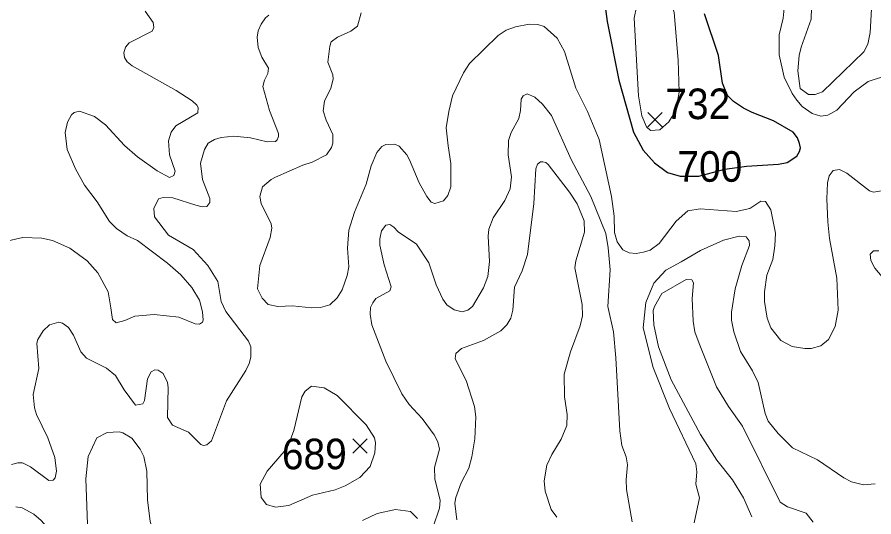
# Model space of a CAD drawing. Extents: x 294.2 to 320.3, y 7482.7 to 7510.7.
# Drawn here: x 303.455 to 305.694, y 7490.851 to 7492.157 of the extents above; entities that cross this region are included whole.
import ezdxf
from ezdxf.enums import TextEntityAlignment as Align

# ---------------------------------------------------------------- set-up
doc = ezdxf.new("R2010")
doc.units = 0
doc.header["$LTSCALE"] = 0.032
for name, color, linetype, lineweight in [('1', 7, 'Continuous', 25), ('2', 7, 'Continuous', 13), ('21', 7, 'Continuous', 25)]:
    doc.layers.add(name, color=color, linetype=linetype, lineweight=lineweight)
doc.layers.add('61', color=7, linetype='Continuous')

msp = doc.modelspace()

# ---------------------------------------------------------------- linework, layer by layer
at = {"layer": '1'}
for points in [[(304.9833, 7492.2509), (304.9973, 7492.1456), (305.0273, 7491.9923), (305.0656, 7491.857), (305.0912, 7491.8098), (305.1211, 7491.7761), (305.1544, 7491.7511), (305.1876, 7491.7413), (305.2367, 7491.7418), (305.3048, 7491.7599), (305.3607, 7491.7675), (305.4443, 7491.7728), (305.467, 7491.7773)], [(305.483, 7491.8564), (305.4317, 7491.8859), (305.3759, 7491.9078), (305.3532, 7491.9198), (305.3268, 7491.9372), (305.3117, 7491.9523), (305.2988, 7491.9848), (305.2883, 7492.0573), (305.2517, 7492.1661)], [(305.467, 7491.7773), (305.4929, 7491.7937), (305.4997, 7491.8058), (305.5019, 7491.8156), (305.4997, 7491.827), (305.4944, 7491.8421), (305.483, 7491.8564)]]:
    msp.add_lwpolyline(points, dxfattribs=at)
at = {"layer": '2'}
for points in [[(305.0675, 7492.1546), (305.079, 7491.9515), (305.0874, 7491.8992), (305.0996, 7491.8704), (305.1101, 7491.8607), (305.1346, 7491.8629), (305.1584, 7491.8838), (305.1762, 7491.9134), (305.1851, 7491.9613), (305.1825, 7492.0448), (305.1722, 7492.1699), (305.1659, 7492.1929), (305.1588, 7492.2056), (305.1429, 7492.2216), (305.1276, 7492.2222), (305.1123, 7492.219), (305.0905, 7492.2075), (305.0739, 7492.1839)], [(304.1066, 7490.8833), (304.0932, 7490.9012), (304.0907, 7490.9364), (304.1086, 7490.9708), (304.1533, 7491.0217), (304.1644, 7491.039), (304.1788, 7491.0768), (304.1992, 7491.1649), (304.2081, 7491.1796), (304.2248, 7491.1924), (304.258, 7491.1879), (304.2918, 7491.1681), (304.3678, 7491.0915), (304.3895, 7491.0577), (304.392, 7491.0449), (304.3901, 7491.0181), (304.378, 7490.9829), (304.3506, 7490.9542), (304.3129, 7490.9319), (304.2861, 7490.9217), (304.2273, 7490.9076), (304.1654, 7490.8808), (304.1303, 7490.8763)]]:
    msp.add_lwpolyline(points, close=True, dxfattribs=at)
for points in [[(305.7188, 7492.002), (305.6792, 7491.9892), (305.6422, 7491.9617), (305.5975, 7491.9139), (305.5733, 7491.9011), (305.5554, 7491.8985), (305.5324, 7491.9055), (305.5062, 7491.9234), (305.4922, 7491.94), (305.48, 7491.9579), (305.4596, 7492.0001), (305.4462, 7492.0588), (305.4468, 7492.1112), (305.457, 7492.1546), (305.4615, 7492.198)], [(303.4203, 7491.5704), (303.4701, 7491.5812), (303.5199, 7491.5793), (303.548, 7491.5735), (303.5927, 7491.5538), (303.638, 7491.5206), (303.6661, 7491.4893), (303.6935, 7491.4395), (303.6999, 7491.3973), (303.705, 7491.3667), (303.714, 7491.3584), (303.737, 7491.3641), (303.7625, 7491.3756), (303.8136, 7491.3801), (303.8775, 7491.373), (303.9209, 7491.3558), (303.9323, 7491.3546), (303.94, 7491.3603), (303.9413, 7491.3648), (303.94, 7491.3871), (303.9323, 7491.4178), (303.9119, 7491.451), (303.8832, 7491.4835), (303.8487, 7491.5142), (303.7695, 7491.5735), (303.7427, 7491.5857), (303.7153, 7491.6048), (303.6968, 7491.6233), (303.6648, 7491.6744), (303.631, 7491.7179), (303.608, 7491.7606), (303.5863, 7491.8111), (303.5812, 7491.8558), (303.5869, 7491.8826), (303.5972, 7491.9017), (303.6042, 7491.9081), (303.6182, 7491.9119), (303.6578, 7491.8973), (303.6865, 7491.8761), (303.7357, 7491.8219), (303.7695, 7491.7919), (303.8213, 7491.7555), (303.8532, 7491.7382), (303.8647, 7491.7434), (303.8679, 7491.7549), (303.8532, 7491.797), (303.8513, 7491.8341), (303.8577, 7491.857), (303.8704, 7491.873), (303.9279, 7491.9068), (303.9285, 7491.9209), (303.9247, 7491.9273), (303.9126, 7491.9387), (303.8711, 7491.9655), (303.7562, 7492.0301), (303.7427, 7492.0409), (303.7363, 7492.0518), (303.7344, 7492.0639), (303.7389, 7492.0786), (303.7484, 7492.0901), (303.8085, 7492.1207), (303.8123, 7492.1303), (303.8104, 7492.1431), (303.79, 7492.173)], [(305.5311, 7492.1827), (305.5298, 7492.152), (305.5043, 7492.0792), (305.4991, 7492.0575), (305.4953, 7492.0167), (305.5011, 7491.9707), (305.5228, 7491.9553), (305.5401, 7491.9553), (305.5598, 7491.9624), (305.6677, 7492.0665), (305.6779, 7492.0869), (305.6843, 7492.1175), (305.6881, 7492.1788)], [(303.9508, 7491.6623), (303.9585, 7491.6732), (303.9591, 7491.6834), (303.9394, 7491.7332), (303.9349, 7491.7753), (303.9451, 7491.8111), (303.9547, 7491.8277), (303.9707, 7491.8372), (303.9886, 7491.8423), (304.0218, 7491.8462), (304.0652, 7491.8417), (304.1086, 7491.8315), (304.1303, 7491.8321), (304.1347, 7491.8366), (304.1386, 7491.8455), (304.1379, 7491.8532), (304.1149, 7491.9132), (304.0977, 7491.9758), (304.1016, 7491.9924), (304.1105, 7492.0103), (304.1124, 7492.0237), (304.0945, 7492.0524), (304.085, 7492.078), (304.083, 7492.1048), (304.0856, 7492.1214), (304.0926, 7492.1392), (304.1041, 7492.1558), (304.113, 7492.1629)], [(304.3544, 7492.1686), (304.3448, 7492.1341), (304.3275, 7492.1207), (304.2925, 7492.1054)], [(304.2752, 7491.972), (304.2586, 7491.9375), (304.2548, 7491.912), (304.2625, 7491.8877), (304.2803, 7491.8507), (304.2803, 7491.8277), (304.2771, 7491.8162), (304.2637, 7491.7976), (304.2261, 7491.7785), (304.2018, 7491.7708), (304.1303, 7491.7389), (304.1188, 7491.7331), (304.0964, 7491.714), (304.0894, 7491.6885), (304.0926, 7491.67), (304.1194, 7491.617), (304.1207, 7491.6055), (304.1169, 7491.5812), (304.0894, 7491.5084), (304.0837, 7491.4471), (304.0958, 7491.4229), (304.1111, 7491.4062), (304.1367, 7491.4005), (304.175, 7491.4031), (304.2248, 7491.3973), (304.2478, 7491.398), (304.272, 7491.405), (304.2912, 7491.4235), (304.3046, 7491.4446), (304.318, 7491.4816), (304.3225, 7491.5046), (304.3186, 7491.5531), (304.3218, 7491.6004), (304.3371, 7491.6476), (304.3678, 7491.7204), (304.3805, 7491.7689), (304.3953, 7491.8034), (304.408, 7491.8194), (304.4189, 7491.8245), (304.4419, 7491.8257), (304.4534, 7491.82), (304.4738, 7491.797), (304.4808, 7491.7843), (304.5057, 7491.7242), (304.5255, 7491.6885), (304.537, 7491.6738), (304.5466, 7491.6706), (304.5696, 7491.677), (304.5804, 7491.691), (304.5887, 7491.714), (304.5887, 7491.7746), (304.5817, 7491.8213), (304.5768, 7491.868), (304.5831, 7491.9106), (304.5932, 7491.9515), (304.6213, 7492.0116), (304.6372, 7492.0358), (304.7126, 7492.1098), (304.733, 7492.1233), (304.7573, 7492.1322), (304.793, 7492.1386), (304.816, 7492.1379), (304.8326, 7492.1328), (304.8664, 7492.1028), (304.8856, 7492.0677), (304.9156, 7491.972), (304.9456, 7491.9107), (304.9763, 7491.8379), (305.0088, 7491.6885), (305.0152, 7491.6374), (305.0165, 7491.594), (305.0228, 7491.5697), (305.0382, 7491.5492), (305.0548, 7491.541), (305.0727, 7491.5397), (305.0918, 7491.5429), (305.1097, 7491.5486), (305.1327, 7491.5652), (305.1774, 7491.624), (305.208, 7491.6514), (305.24, 7491.6565), (305.3345, 7491.6495), (305.3702, 7491.6572), (305.3983, 7491.6763), (305.4104, 7491.6751), (305.4251, 7491.654), (305.4366, 7491.5927), (305.4353, 7491.5595), (305.4296, 7491.5238), (305.4143, 7491.4829), (305.4079, 7491.4395), (305.4079, 7491.4139), (305.4155, 7491.3705), (305.4245, 7491.345), (305.4506, 7491.3124)], [(304.2925, 7492.1054), (304.2758, 7492.0926), (304.2727, 7492.0818), (304.2676, 7492.0396), (304.2803, 7492.0064), (304.2809, 7491.995), (304.2752, 7491.972)], [(304.8083, 7491.9483), (304.7879, 7491.9566), (304.7777, 7491.9515), (304.772, 7491.9426), (304.7707, 7491.9132), (304.7662, 7491.8928), (304.7464, 7491.8558), (304.7394, 7491.8353), (304.7381, 7491.797), (304.747, 7491.7396), (304.7432, 7491.7089), (304.7298, 7491.6783), (304.6992, 7491.6323), (304.6883, 7491.6029), (304.6857, 7491.585), (304.6896, 7491.5186), (304.6851, 7491.4791), (304.6736, 7491.4497), (304.6449, 7491.4012), (304.6334, 7491.3916), (304.618, 7491.3871), (304.597, 7491.3922), (304.5785, 7491.405), (304.5676, 7491.4203), (304.5504, 7491.4574), (304.5312, 7491.5148), (304.4987, 7491.5639), (304.4514, 7491.596), (304.4393, 7491.6087), (304.4291, 7491.6151), (304.4189, 7491.6138), (304.4074, 7491.5984), (304.4029, 7491.5774), (304.4035, 7491.5614), (304.4144, 7491.5097), (304.4323, 7491.4522), (304.4291, 7491.442), (304.3927, 7491.4216), (304.3844, 7491.4101), (304.3787, 7491.3979), (304.3774, 7491.3807), (304.3818, 7491.3526), (304.4188, 7491.2581), (304.4604, 7491.1726), (304.4801, 7491.1445), (304.5133, 7491.1081), (304.5453, 7491.0653), (304.5549, 7491.0475), (304.5593, 7491.0283), (304.5459, 7490.9798), (304.5472, 7490.9504), (304.5606, 7490.8942), (304.5593, 7490.8738), (304.5421, 7490.8253)], [(304.9999, 7491.5544), (304.9935, 7491.5914), (304.9546, 7491.6885), (304.9028, 7491.7855), (304.8517, 7491.9005), (304.8281, 7491.9298), (304.8083, 7491.9483)], [(304.8658, 7490.8502), (304.8511, 7490.87), (304.8351, 7490.9185), (304.8326, 7490.9453), (304.8396, 7490.9862), (304.8524, 7491.0143), (304.8773, 7491.0538), (304.8913, 7491.0896), (304.8926, 7491.119), (304.8856, 7491.1649), (304.8849, 7491.2237), (304.9015, 7491.2824), (304.9265, 7491.3501), (304.9322, 7491.3769), (304.9316, 7491.4063), (304.913, 7491.502), (304.9156, 7491.5199), (304.938, 7491.5953), (304.9373, 7491.6246), (304.9188, 7491.6693), (304.899, 7491.7), (304.8428, 7491.7721), (304.8364, 7491.7778), (304.8288, 7491.7791), (304.823, 7491.7791), (304.8147, 7491.7734), (304.8103, 7491.7612), (304.8052, 7491.6706), (304.7886, 7491.5365), (304.7751, 7491.4944), (304.7547, 7491.4516), (304.7509, 7491.391), (304.7457, 7491.3705), (304.7351, 7491.3532), (304.7196, 7491.3373), (304.6743, 7491.3124), (304.6168, 7491.2907), (304.6014, 7491.2779), (304.6002, 7491.2639), (304.6289, 7491.2071), (304.65, 7491.1394), (304.6538, 7491.1126), (304.6512, 7491.0551), (304.6436, 7491.0079), (304.6353, 7490.9785), (304.6155, 7490.9402), (304.6014, 7490.9019), (304.5989, 7490.8865), (304.604, 7490.8431)], [(305.5924, 7491.3488), (305.6007, 7491.391), (305.5975, 7491.4752), (305.5777, 7491.5787), (305.5732, 7491.6221), (305.5707, 7491.6821), (305.5726, 7491.7242), (305.577, 7491.7421), (305.5879, 7491.7568), (305.6045, 7491.7593), (305.6231, 7491.7497), (305.6824, 7491.7032), (305.6933, 7491.6999), (305.729, 7491.7057)], [(303.813, 7491.6572), (303.8251, 7491.6827), (303.8366, 7491.6859), (303.8621, 7491.6846), (303.9222, 7491.6655), (303.9388, 7491.6616), (303.9508, 7491.6623)], [(303.4407, 7490.9881), (303.4573, 7490.9919), (303.4694, 7490.9919), (303.4905, 7490.9817), (303.5378, 7490.9459), (303.5493, 7490.9465), (303.555, 7490.9529), (303.5582, 7490.9708), (303.5543, 7491.0066), (303.5359, 7491.0577), (303.5058, 7491.119), (303.5007, 7491.1356), (303.4976, 7491.1713), (303.5122, 7491.239), (303.5071, 7491.3054), (303.5091, 7491.3143), (303.5231, 7491.3373), (303.5397, 7491.3533), (303.5646, 7491.3597), (303.5735, 7491.3577), (303.5895, 7491.3456), (303.6023, 7491.3264), (303.622, 7491.2824), (303.6367, 7491.2658), (303.6885, 7491.2396), (303.7127, 7491.2205), (303.7351, 7491.1828), (303.7644, 7491.1432), (303.7842, 7491.1464), (303.788, 7491.1553), (303.7964, 7491.2122), (303.8059, 7491.2301), (303.8149, 7491.2351), (303.8238, 7491.2345), (303.8372, 7491.2262), (303.848, 7491.202), (303.85, 7491.1892), (303.8487, 7491.1106), (303.8615, 7491.0908), (303.903, 7491.0723), (303.9355, 7491.0404), (303.9426, 7491.0372), (303.9508, 7491.0391), (303.9636, 7491.05), (304.0026, 7491.1547), (304.053, 7491.2332), (304.0613, 7491.2518), (304.0658, 7491.2684), (304.0658, 7491.2952), (304.06, 7491.3099), (304.0007, 7491.3877), (303.9885, 7491.4139), (303.9796, 7491.4663), (303.954, 7491.5084), (303.9151, 7491.5499), (303.8506, 7491.5876), (303.8142, 7491.6349), (303.813, 7491.6572)], [(305.6971, 7490.937), (305.6665, 7490.9344), (305.6358, 7490.9427), (305.6154, 7490.9529), (305.5464, 7491.0002), (305.4813, 7491.0315), (305.4436, 7491.0685), (305.4181, 7491.1011), (305.4098, 7491.1215), (305.3913, 7491.202), (305.3772, 7491.2326), (305.3453, 7491.2837), (305.328, 7491.3348), (305.3223, 7491.3654), (305.3216, 7491.3858), (305.3313, 7491.4471), (305.3491, 7491.5084), (305.3689, 7491.5608), (305.3683, 7491.5729), (305.3606, 7491.5831), (305.3421, 7491.585), (305.3013, 7491.5742), (305.2412, 7491.5474), (305.1902, 7491.518), (305.1506, 7491.4956), (305.1186, 7491.4618), (305.0982, 7491.4114), (305.0912, 7491.345), (305.1173, 7491.2415), (305.1595, 7491.1343), (305.2291, 7490.99), (305.231, 7490.9683), (305.2284, 7490.9364), (305.2386, 7490.9006), (305.2246, 7490.8355)], [(305.0624, 7490.838), (305.0478, 7490.9223), (305.0465, 7490.9491), (305.0503, 7490.9874), (305.0471, 7491.0079), (305.0356, 7491.0372), (305.0299, 7491.0755), (305.0197, 7491.2671), (305.0133, 7491.3348), (304.9986, 7491.4012), (305.005, 7491.4969), (304.9999, 7491.5544)], [(305.7073, 7491.5461), (305.6926, 7491.5461), (305.6843, 7491.5378)], [(305.6843, 7491.5378), (305.6856, 7491.5212), (305.6965, 7491.5008), (305.768, 7491.4165), (305.775, 7491.3961), (305.7693, 7491.3756), (305.7507, 7491.3348)], [(305.5356, 7490.8368), (305.5171, 7490.8604), (305.4685, 7490.8776), (305.4487, 7490.8891), (305.3504, 7491.0883), (305.314, 7491.1394), (305.2827, 7491.1905), (305.2374, 7491.3041), (305.2265, 7491.3348), (305.222, 7491.3629), (305.2195, 7491.4216), (305.2227, 7491.4624), (305.2182, 7491.4707), (305.2035, 7491.4714), (305.1403, 7491.435), (305.1206, 7491.4012), (305.1173, 7491.3909), (305.1193, 7491.3526), (305.1308, 7491.2952), (305.164, 7491.2096), (305.2412, 7491.0666), (305.284, 7490.9989), (305.3242, 7490.9479), (305.3536, 7490.9006), (305.3753, 7490.8508)], [(305.4506, 7491.3124), (305.48, 7491.2964), (305.5132, 7491.2907), (305.5298, 7491.2913), (305.5554, 7491.2977), (305.5758, 7491.3143), (305.5924, 7491.3488)], [(303.8328, 7490.7882), (303.8129, 7490.8105), (303.8034, 7490.8393), (303.7957, 7490.8955), (303.7944, 7490.9708), (303.7862, 7491.0091), (303.7766, 7491.0283), (303.7555, 7491.0564), (303.7319, 7491.0711), (303.7217, 7491.0736), (303.691, 7491.0717), (303.6635, 7491.0576), (303.6412, 7491.0091), (303.6348, 7490.9504), (303.6399, 7490.8087), (303.6316, 7490.7754), (303.6157, 7490.7633), (303.5978, 7490.7633), (303.5799, 7490.7748), (303.5614, 7490.792), (303.5186, 7490.8418), (303.4988, 7490.8578), (303.4688, 7490.8744), (303.4522, 7490.8776)], [(304.5019, 7490.847), (304.4834, 7490.8648), (304.4444, 7490.8699), (304.3959, 7490.8597), (304.3576, 7490.8412)]]:
    msp.add_lwpolyline(points, dxfattribs=at)
at = {"layer": '21'}
for p, q in [((305.1032, 7491.9078), (305.1407, 7491.8703)), ((305.1407, 7491.9078), (305.1032, 7491.8703)), ((304.3325, 7491.0549), (304.37, 7491.0174)), ((304.37, 7491.0549), (304.3325, 7491.0174))]:
    msp.add_line(p, q, dxfattribs=at)

# ---------------------------------------------------------------- texts
at = {"layer": '61', "width": 0.95}
for s, p in [('732', (305.2337, 7491.8907)), ('700', (305.2653, 7491.727)), ('689', (304.2319, 7490.9754))]:
    msp.add_text(s, height=0.08, dxfattribs=at).set_placement(p, align=Align.CENTER)

doc.saveas('drawing.dxf')
